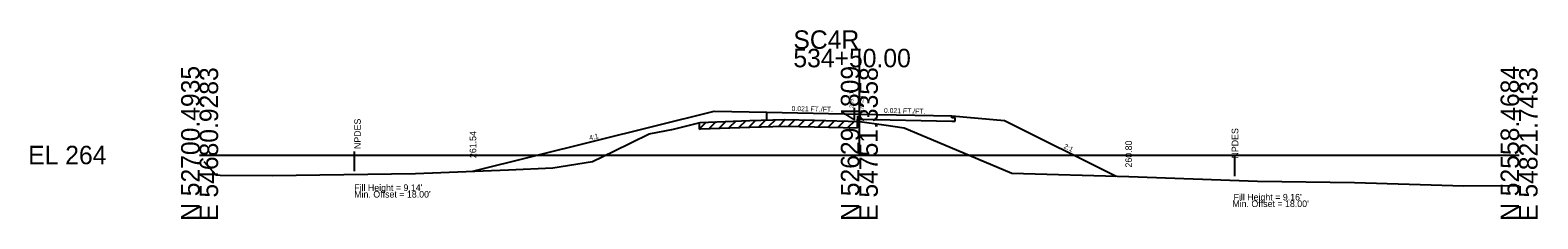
# Model space of a CAD drawing. Extents: x 7498 to 13027, y 90095 to 109625.
# Drawn here: x 9498.3 to 9726.8, y 104595.5 to 104624.1 of the extents above; entities that cross this region are included whole.
import ezdxf

# ---------------------------------------------------------------- set-up
doc = ezdxf.new("R2010")
doc.units = 0
for name, color, linetype in [('Level 10', 7, 'Continuous'), ('Level 11', 7, 'Continuous'), ('Level 12', 7, 'Continuous'), ('Level 32', 7, 'Continuous'), ('Level 33', 7, 'Continuous'), ('Level 50', 7, 'Continuous'), ('Level 53', 7, 'Continuous'), ('Level 55', 7, 'Continuous'), ('Level 59', 7, 'Continuous'), ('Level 6', 7, 'Continuous'), ('Level 60', 7, 'Continuous'), ('Level 61', 7, 'Continuous'), ('Level 63', 7, 'Continuous'), ('Level 7', 7, 'Continuous')]:
    doc.layers.add(name, color=color, linetype=linetype)

msp = doc.modelspace()

# ---------------------------------------------------------------- linework, layer by layer
at = {"layer": 'Level 11'}
for p, q in [((9609.99, 104610.46), (9609.99, 104611.67)), ((9637.99, 104610.79), (9637.99, 104611.09)), ((9638.49, 104610.78), (9637.99, 104610.79)), ((9637.99, 104610.31), (9638.49, 104610.3)), ((9638.49, 104610.3), (9638.49, 104610.78))]:
    msp.add_line(p, q, dxfattribs=at)
at = {"layer": 'Level 12'}
for p, q in [((9623.72, 104610.28), (9623.72, 104610.61)), ((9623.72, 104610.61), (9623.99, 104610.6)), ((9623.99, 104610.6), (9637.99, 104610.31))]:
    msp.add_line(p, q, dxfattribs=at)
at = {"layer": 'Level 53'}
msp.add_line((9623.72, 104611.09), (9623.72, 104610.28), dxfattribs=at)
at = {"layer": 'Level 55'}
for p, q in [((9547.42, 104605.7), (9547.42, 104602.7)), ((9680.92, 104601.96), (9680.92, 104604.96))]:
    msp.add_line(p, q, dxfattribs=at)
at = {"layer": 'Level 59'}
for p, q in [((9609.99, 104611.67), (9623.99, 104611.38)), ((9623.99, 104611.38), (9637.99, 104611.09))]:
    msp.add_line(p, q, dxfattribs=at)
at = {"layer": 'Level 6'}
for p, q in [((9601.99, 104611.84), (9609.99, 104611.67)), ((9637.99, 104611.09), (9645.99, 104610.42))]:
    msp.add_line(p, q, dxfattribs=at)
at = {"layer": 'Level 60'}
for p, q in [((9599.87, 104610.12), (9607.41, 104610.39)), ((9607.41, 104610.39), (9612.59, 104610.53)), ((9612.59, 104610.53), (9617.21, 104610.45)), ((9617.21, 104610.45), (9623.99, 104610.27)), ((9623.99, 104610.27), (9627.71, 104609.72)), ((9586.76, 104605.74), (9592.14, 104608.37)), ((9592.14, 104608.37), (9595.81, 104609.1)), ((9595.81, 104609.1), (9599.87, 104610.12)), ((9627.71, 104609.72), (9630.79, 104609.3)), ((9630.79, 104609.3), (9636.81, 104606.77)), ((9583.53, 104604.17), (9586.76, 104605.74)), ((9636.81, 104606.77), (9647.09, 104602.38)), ((9524.64, 104604.17), (9526.46, 104602.15)), ((9577.51, 104603.21), (9583.53, 104604.17)), ((9526.46, 104602.15), (9527.11, 104602.11)), ((9527.11, 104602.11), (9534.97, 104602.05)), ((9534.97, 104602.05), (9556.73, 104602.37)), ((9556.73, 104602.37), (9570.8, 104602.9)), ((9570.8, 104602.9), (9577.51, 104603.21)), ((9647.09, 104602.38), (9664.86, 104601.91)), ((9664.86, 104601.91), (9684.32, 104601.2)), ((9684.32, 104601.2), (9699.02, 104600.99)), ((9699.02, 104600.99), (9715.6, 104600.5)), ((9715.6, 104600.5), (9723.99, 104600.51))]:
    msp.add_line(p, q, dxfattribs=at)
at = {"layer": 'Level 61'}
for p, q in [((9605.27, 104610.31), (9604.23, 104609.28)), ((9606.77, 104610.37), (9605.73, 104609.33)), ((9608.26, 104610.41), (9607.23, 104609.39)), ((9609.76, 104610.45), (9608.73, 104609.43)), ((9611.27, 104610.5), (9610.24, 104609.47)), ((9612.76, 104610.53), (9611.74, 104609.51)), ((9614.23, 104610.5), (9613.24, 104609.52)), ((9615.73, 104610.48), (9614.74, 104609.49)), ((9617.23, 104610.45), (9616.25, 104609.47)), ((9618.72, 104610.41), (9617.75, 104609.44)), ((9620.22, 104610.37), (9619.25, 104609.4)), ((9621.73, 104610.33), (9620.75, 104609.36)), ((9623.23, 104610.29), (9622.25, 104609.32)), ((9623.72, 104609.28), (9623.72, 104610.28)), ((9600.79, 104610.15), (9599.72, 104609.08)), ((9599.72, 104610.08), (9599.72, 104609.08)), ((9599.72, 104609.08), (9599.87, 104609.12)), ((9599.87, 104609.12), (9607.41, 104609.39)), ((9602.26, 104610.21), (9601.22, 104609.17)), ((9603.76, 104610.26), (9602.73, 104609.22)), ((9607.41, 104609.39), (9612.59, 104609.53)), ((9612.59, 104609.53), (9617.21, 104609.45)), ((9617.21, 104609.45), (9623.72, 104609.28))]:
    msp.add_line(p, q, dxfattribs=at)
at = {"layer": 'Level 63'}
for p, q in [((9623.99, 104605.16), (9623.99, 104621.28)), ((9523.99, 104605.16), (9623.99, 104605.16)), ((9623.99, 104605.16), (9723.99, 104605.16))]:
    msp.add_line(p, q, dxfattribs=at)
at = {"layer": 'Level 7'}
for p, q in [((9565.42, 104602.7), (9601.99, 104611.84)), ((9645.99, 104610.42), (9662.92, 104601.96))]:
    msp.add_line(p, q, dxfattribs=at)

# ---------------------------------------------------------------- texts
at = {"layer": 'Level 10'}
msp.add_text('269.11', height=0.6, rotation=90, dxfattribs=at).set_placement((9623.08, 104612.3))
at = {"layer": 'Level 32'}
for s, rotation, p in [('0.021 FT./FT.', 358.8084, (9613.71, 104611.85)), ('0.021 FT./FT.', 358.8084, (9627.71, 104611.56)), ('4:1', 14.0362, (9583.13, 104607.38)), ('2:1', 333.435, (9654.9, 104606.25))]:
    msp.add_text(s, height=0.75, rotation=rotation, dxfattribs=at).set_placement(p)
at = {"layer": 'Level 33'}
for s, p in [('261.54', (9565.92, 104604.7)), ('260.80', (9665.31, 104603.26))]:
    msp.add_text(s, height=1, rotation=90, dxfattribs=at).set_placement(p)
at = {"layer": 'Level 50'}
for p in [(9548.42, 104605.7), (9681.43, 104604.26)]:
    msp.add_text(' NPDES', height=1, rotation=90, dxfattribs=at).set_placement(p)
for s, p in [("Fill Height = 9.14' ", (9547.42, 104599.7)), ("Min. Offset = 18.00' ", (9547.42, 104598.7)), ("Fill Height = 9.16' ", (9680.71, 104598.26)), ("Min. Offset = 18.00' ", (9680.52, 104597.26))]:
    msp.add_text(s, height=1, dxfattribs=at).set_placement(p)
at = {"layer": 'Level 59'}
msp.add_text(' 270.23', height=0.6, rotation=90, dxfattribs=at).set_placement((9624.59, 104611.38))
at = {"layer": 'Level 63'}
for s, p in [('SC4R', (9613.99, 104621.28)), ('534+50.00', (9613.99, 104618.48)), ('EL 264', (9498, 104603.76))]:
    msp.add_text(s, height=2.8, dxfattribs=at).set_placement(p)
for s, p in [('N 52700.4935', (9523.99, 104595.16)), ('E 54680.9283', (9526.79, 104595.16)), ('N 52629.4809', (9623.99, 104595.16)), ('E 54751.3358', (9626.79, 104595.16)), ('N 52558.4684', (9723.99, 104595.16)), ('E 54821.7433', (9726.79, 104595.16))]:
    msp.add_text(s, height=2.8, rotation=90, dxfattribs=at).set_placement(p)

doc.saveas('drawing.dxf')
